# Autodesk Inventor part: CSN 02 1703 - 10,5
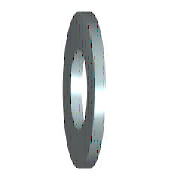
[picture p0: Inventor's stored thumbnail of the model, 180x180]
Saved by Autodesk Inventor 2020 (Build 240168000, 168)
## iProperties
Created: 2019-01
Part Number: CSN 02 1703 - 10,5
Material: Ocel, měkká
Description: Podložky pro šrouby s válcovou a půlkulovou hlavou
Document SubType Name: Modeling
Standard: CSN 02 1703
Designer: doma
Standards Organization: CSN
Language: cs-CZ
Size Designation: 10,5
Categories: <MemberInstance><Categories><Category DisplayName="Spojovací materiál" InternalName="e4da775c-781d-43d5-af7c-5136215cf5a6" Mnemonic="FSTN"><Category DisplayName
Density: 7.85 g/cm^3
Appearance: Pololeštěná
Mass: 2.6357 g
Surface Area: 5.14828 cm^2
Volume: 0.335758 cm^3
IsCustomPart: 0
Author: doma
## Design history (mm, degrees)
sketch "Náčrt"
  geometry: C1 r 9 at (0, 0); C2 r 5.25 at (0, 0); 1 further point
  constraints: 2 centre point, 2 coincident
  dimensions: "d0" = 10.5 diameter of C2 (= SD1); "d1" = 18 diameter of C1 (= SD2)
extrude "Těleso" new body sketch "Náčrt" distance "d2" = 2 (= SD); taper "d3" = 0 deg
workaxis "Work Axis1"
workplane "Work Plane1"
body "Solid1"
other parameters: "SD1" = 10.5 [user parameter; used in 1 equation term], "SD2" = 18 [user parameter; used in 1 equation term], "SD" = 2 [user parameter; used in 1 equation term], "d4" = 0, "d5" = 0, "d6" = 0, "d7" = 0
